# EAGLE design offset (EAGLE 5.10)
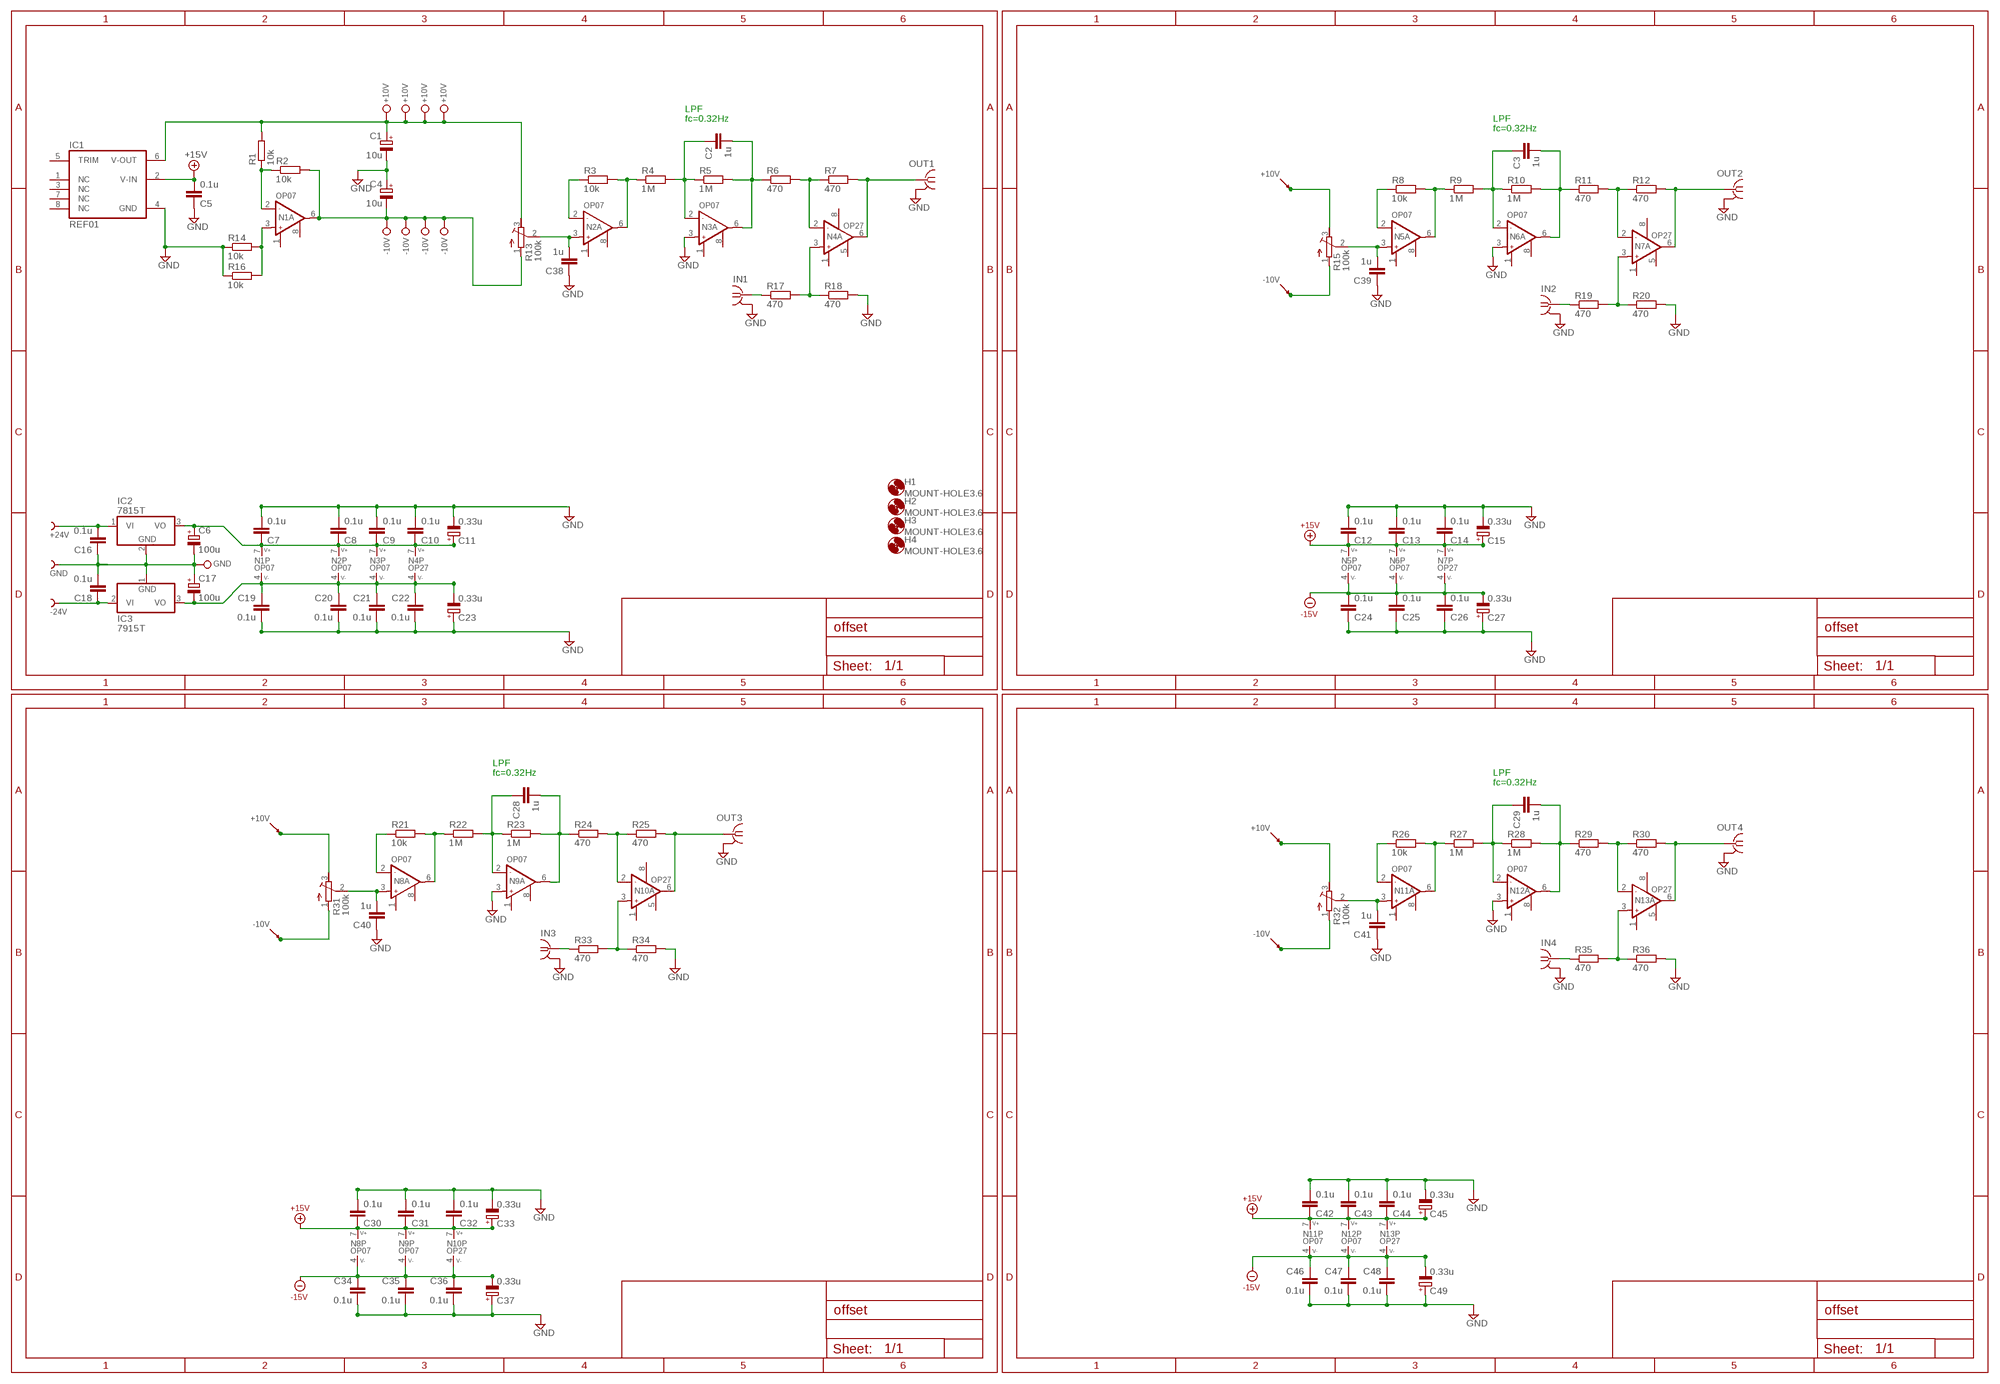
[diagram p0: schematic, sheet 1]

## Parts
+24V  XPIN  [XPIN]
-24V  XPIN  [XPIN]
C1  10u  CPOL-EUE5-5  [E5-5]
C2  1u  C-EU050-035X075  [C050-035X075]
C3  1u  C-EU050-035X075  [C050-035X075]
C4  10u  CPOL-EUE5-5  [E5-5]
C5  0.1u  C-EU050-035X075  [C050-035X075]
C6  100u  CPOL-EUE5-8.5  [E5-8,5]
C7  0.1u  C-EU050-035X075  [C050-035X075]
C8  0.1u  C-EU050-035X075  [C050-035X075]
C9  0.1u  C-EU050-035X075  [C050-035X075]
C10  0.1u  C-EU050-035X075  [C050-035X075]
C11  0.33u  CPOL-EUE5-5  [E5-5]
C12  0.1u  C-EU050-035X075  [C050-035X075]
C13  0.1u  C-EU050-035X075  [C050-035X075]
C14  0.1u  C-EU050-035X075  [C050-035X075]
C15  0.33u  CPOL-EUE5-5  [E5-5]
C16  0.1u  C-EU050-035X075  [C050-035X075]
C17  100u  CPOL-EUE5-8.5  [E5-8,5]
C18  0.1u  C-EU050-035X075  [C050-035X075]
C19  0.1u  C-EU050-035X075  [C050-035X075]
C20  0.1u  C-EU050-035X075  [C050-035X075]
C21  0.1u  C-EU050-035X075  [C050-035X075]
C22  0.1u  C-EU050-035X075  [C050-035X075]
C23  0.33u  CPOL-EUE5-5  [E5-5]
C24  0.1u  C-EU050-035X075  [C050-035X075]
C25  0.1u  C-EU050-035X075  [C050-035X075]
C26  0.1u  C-EU050-035X075  [C050-035X075]
C27  0.33u  CPOL-EUE5-5  [E5-5]
C28  1u  C-EU050-035X075  [C050-035X075]
C29  1u  C-EU050-035X075  [C050-035X075]
C30  0.1u  C-EU050-035X075  [C050-035X075]
C31  0.1u  C-EU050-035X075  [C050-035X075]
C32  0.1u  C-EU050-035X075  [C050-035X075]
C33  0.33u  CPOL-EUE5-5  [E5-5]
C34  0.1u  C-EU050-035X075  [C050-035X075]
C35  0.1u  C-EU050-035X075  [C050-035X075]
C36  0.1u  C-EU050-035X075  [C050-035X075]
C37  0.33u  CPOL-EUE5-5  [E5-5]
C38  1u  C-EU050-035X075  [C050-035X075]
C39  1u  C-EU050-035X075  [C050-035X075]
C40  1u  C-EU050-035X075  [C050-035X075]
C41  1u  C-EU050-035X075  [C050-035X075]
C42  0.1u  C-EU050-035X075  [C050-035X075]
C43  0.1u  C-EU050-035X075  [C050-035X075]
C44  0.1u  C-EU050-035X075  [C050-035X075]
C45  0.33u  CPOL-EUE5-5  [E5-5]
C46  0.1u  C-EU050-035X075  [C050-035X075]
C47  0.1u  C-EU050-035X075  [C050-035X075]
C48  0.1u  C-EU050-035X075  [C050-035X075]
C49  0.33u  CPOL-EUE5-5  [E5-5]
GND  XPIN  [XPIN]
H1  MOUNT-HOLE3.6  [3,6]
H2  MOUNT-HOLE3.6  [3,6]
H3  MOUNT-HOLE3.6  [3,6]
H4  MOUNT-HOLE3.6  [3,6]
IC1  REF01  REF01HP  [DIL08]
IC2  7815T  [TO220H]
IC3  7915T  [TO220H]
IN1  BU-SMA-V  [BU-SMA-V]
IN2  BU-SMA-V  [BU-SMA-V]
IN3  BU-SMA-V  [BU-SMA-V]
IN4  BU-SMA-V  [BU-SMA-V]
N1  OP07  [DIP08_N]
N2  OP07  [DIP08_N]
N3  OP07  [DIP08_N]
N4  OP27  AD797  [DIP08_L]
N5  OP07  [DIP08_N]
N6  OP07  [DIP08_N]
N7  OP27  AD797  [DIP08_L]
N8  OP07  [DIP08_N]
N9  OP07  [DIP08_N]
N10  OP27  AD797  [DIP08_L]
N11  OP07  [DIP08_N]
N12  OP07  [DIP08_N]
N13  OP27  AD797  [DIP08_L]
OUT1  BU-SMA-V  [BU-SMA-V]
OUT2  BU-SMA-V  [BU-SMA-V]
OUT3  BU-SMA-V  [BU-SMA-V]
OUT4  BU-SMA-V  [BU-SMA-V]
R1  10k  R-EU_0207/7  [0207/7]
R2  10k  R-EU_0207/7  [0207/7]
R3  10k  R-EU_0207/7  [0207/7]
R4  1M  R-EU_0207/7  [0207/7]
R5  1M  R-EU_0207/7  [0207/7]
R6  470  R-EU_0207/7  [0207/7]
R7  470  R-EU_0207/7  [0207/7]
R8  10k  R-EU_0207/7  [0207/7]
R9  1M  R-EU_0207/7  [0207/7]
R10  1M  R-EU_0207/7  [0207/7]
R11  470  R-EU_0207/7  [0207/7]
R12  470  R-EU_0207/7  [0207/7]
R13  100k  R-TRIMM3299W  [RTRIM3299W]
R14  10k  R-EU_0207/7  [0207/7]
R15  100k  R-TRIMM3299W  [RTRIM3299W]
R16  10k  R-EU_0207/7  [0207/7]
R17  470  R-EU_0207/7  [0207/7]
R18  470  R-EU_0207/7  [0207/7]
R19  470  R-EU_0207/7  [0207/7]
R20  470  R-EU_0207/7  [0207/7]
R21  10k  R-EU_0207/7  [0207/7]
R22  1M  R-EU_0207/7  [0207/7]
R23  1M  R-EU_0207/7  [0207/7]
R24  470  R-EU_0207/7  [0207/7]
R25  470  R-EU_0207/7  [0207/7]
R26  10k  R-EU_0207/7  [0207/7]
R27  1M  R-EU_0207/7  [0207/7]
R28  1M  R-EU_0207/7  [0207/7]
R29  470  R-EU_0207/7  [0207/7]
R30  470  R-EU_0207/7  [0207/7]
R31  100k  R-TRIMM3299W  [RTRIM3299W]
R32  100k  R-TRIMM3299W  [RTRIM3299W]
R33  470  R-EU_0207/7  [0207/7]
R34  470  R-EU_0207/7  [0207/7]
R35  470  R-EU_0207/7  [0207/7]
R36  470  R-EU_0207/7  [0207/7]
X1  +10V  XPIN1  [1PIN]
X2  +10V  XPIN1  [1PIN]
X3  +10V  XPIN1  [1PIN]
X4  +10V  XPIN1  [1PIN]
X5  -10V  XPIN1  [1PIN]
X6  -10V  XPIN1  [1PIN]
X7  -10V  XPIN1  [1PIN]
X8  -10V  XPIN1  [1PIN]
X9  GND  XPIN1  [1PIN]

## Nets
GND: C1.- C4.+ C5.1 C6.- C7.2 C8.2 C9.2 C10.2 C11.- C12.2 C13.2 C14.2 C15.- C16.1 C17.+ C18.2 C19.2 C20.2 C21.2 C22.2 C23.+ C24.1 C25.1 C26.1 C27.+ C30.2 C31.2 C32.2 C33.- C34.2 C35.2 C36.2 C37.+ C38.1 C39.1 C40.1 C41.1 C42.2 C43.2 C44.2 C45.- C46.2 C47.2 C48.2 C49.+ GND.1 IC1.4(GND) IC2.2(GND) IC3.1(GND) IN1.2(GND) IN2.2(GND) IN3.2(GND) IN4.2(GND) N3.3(A:OP+) N6.3(A:OP+) N9.3(A:OP+) N12.3(A:OP+) OUT1.2(GND) OUT2.2(GND) OUT3.2(GND) OUT4.2(GND) R14.1 R16.1 R18.2 R20.2 R34.2 R36.2 X9.1
N$1: C1.+ IC1.6(V-OUT) R1.2 R13.3(A) R15.3(A) R31.3(A) R32.3(A) X1.1 X2.1 X3.1 X4.1
N$2: N7.6(A:OPO) OUT2.1 R12.2
N$3: C4.- N1.6(A:OPO) R2.2 R13.1(E) R15.1(E) R31.1(E) R32.1(E) X5.1 X6.1 X7.1 X8.1
N$4: C2.1 N3.2(A:OP-) R4.2 R5.1
N$5: C2.2 N3.6(A:OPO) R5.2 R6.1
N$6: C39.2 N5.3(A:OP+) R15.2(S)
N$7: N5.2(A:OP-) R8.1
N$8: N5.6(A:OPO) R8.2 R9.1
N$9: N7.3(A:OP+) R19.2 R20.1
N$10: IN2.1 R19.1
N$11: C38.2 N2.3(A:OP+) R13.2(S)
N$12: N2.2(A:OP-) R3.1
N$13: N1.3(A:OP+) R14.2 R16.2
N$14: N2.6(A:OPO) R3.2 R4.1
N$15: N7.2(A:OP-) R11.2 R12.1
N$16: N4.6(A:OPO) OUT1.1 R7.2
N$17: N1.2(A:OP-) R1.1 R2.1
N$20: -24V.1 C18.1 IC3.2(VI)
N$21: +24V.1 C16.2 IC2.1(VI)
N$22: C3.1 N6.2(A:OP-) R9.2 R10.1
N$23: C3.2 N6.6(A:OPO) R10.2 R11.1
N$24: N10.6(A:OPO) OUT3.1 R25.2
N$25: N4.3(A:OP+) R17.2 R18.1
N$26: C40.2 N8.3(A:OP+) R31.2(S)
N$27: N8.2(A:OP-) R21.1
N$28: N8.6(A:OPO) R21.2 R22.1
N$29: IN1.1 R17.1
N$30: N4.2(A:OP-) R6.2 R7.1
N$31: N10.3(A:OP+) R33.2 R34.1
N$32: IN3.1 R33.1
N$33: N10.2(A:OP-) R24.2 R25.1
N$36: C28.1 N9.2(A:OP-) R22.2 R23.1
N$37: C28.2 N9.6(A:OPO) R23.2 R24.1
N$38: N13.6(A:OPO) OUT4.1 R30.2
N$39: C41.2 N11.3(A:OP+) R32.2(S)
N$40: N11.2(A:OP-) R26.1
N$41: N11.6(A:OPO) R26.2 R27.1
N$42: N13.3(A:OP+) R35.2 R36.1
N$43: IN4.1 R35.1
N$44: N13.2(A:OP-) R29.2 R30.1
N$47: C29.1 N12.2(A:OP-) R27.2 R28.1
N$48: C29.2 N12.6(A:OPO) R28.2 R29.1
V+: C5.2 C6.+ C7.1 C8.1 C9.1 C10.1 C11.+ C12.1 C13.1 C14.1 C15.+ C30.1 C31.1 C32.1 C33.+ C42.1 C43.1 C44.1 C45.+ IC1.2(V-IN) IC2.3(VO) N1.7(P:V+) N2.7(P:V+) N3.7(P:V+) N4.7(P:V+) N5.7(P:V+) N6.7(P:V+) N7.7(P:V+) N8.7(P:V+) N9.7(P:V+) N10.7(P:V+) N11.7(P:V+) N12.7(P:V+) N13.7(P:V+) ; supply symbol labelled +15V, V+15V
V-: C17.- C19.1 C20.1 C21.1 C22.1 C23.- C24.2 C25.2 C26.2 C27.- C34.1 C35.1 C36.1 C37.- C46.1 C47.1 C48.1 C49.- IC3.3(VO) N1.4(P:V-) N2.4(P:V-) N3.4(P:V-) N4.4(P:V-) N5.4(P:V-) N6.4(P:V-) N7.4(P:V-) N8.4(P:V-) N9.4(P:V-) N10.4(P:V-) N11.4(P:V-) N12.4(P:V-) N13.4(P:V-) ; supply symbol labelled V-15V
Unconnected: IC1.1(NC) IC1.3(NC) IC1.5(TRIM) IC1.7(NC) IC1.8(NC) N1.1(A:OPC1) N1.8(A:OPC2) N2.1(A:OPC1) N2.8(A:OPC2) N3.1(A:OPC1) N3.8(A:OPC2) N4.1(A:OPC1) N4.5(A:OPC2) N4.8(A:OPF) N5.1(A:OPC1) N5.8(A:OPC2) N6.1(A:OPC1) N6.8(A:OPC2) N7.1(A:OPC1) N7.5(A:OPC2) N7.8(A:OPF) N8.1(A:OPC1) N8.8(A:OPC2) N9.1(A:OPC1) N9.8(A:OPC2) N10.1(A:OPC1) N10.5(A:OPC2) N10.8(A:OPF) N11.1(A:OPC1) N11.8(A:OPC2) N12.1(A:OPC1) N12.8(A:OPC2) N13.1(A:OPC1) N13.5(A:OPC2) N13.8(A:OPF)

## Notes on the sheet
- LPF
- fc=0.32Hz | LPF
- fc=0.32Hz
- LPF
- fc=0.32Hz | LPF
- fc=0.32Hz

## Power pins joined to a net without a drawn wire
GND: IN1.3(GND) IN1.4(GND) IN1.5(GND) IN2.3(GND) IN2.4(GND) IN2.5(GND) IN3.3(GND) IN3.4(GND) IN3.5(GND) IN4.3(GND) IN4.4(GND) IN4.5(GND) OUT1.3(GND) OUT1.4(GND) OUT1.5(GND) OUT2.3(GND) OUT2.4(GND) OUT2.5(GND) OUT3.3(GND) OUT3.4(GND) OUT3.5(GND) OUT4.3(GND) OUT4.4(GND) OUT4.5(GND)

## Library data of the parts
+24V -24V GND = DIVERS:XPIN
C1 C4 C6 C11 C15 C17 C23 C27 C33 C37 C45 C49 = rcl:CPOL-EU: POLARIZED CAPACITOR, European symbol
C2 C3 C5 C7-C10 C12-C14 C16 C18-C22 C24-C26 C28-C32 C34-C36 C38-C44 C46-C48 = rcl:C-EU: CAPACITOR, European symbol
H1-H4 = holes:MOUNT-HOLE: MOUNTING HOLE with drill center marker
IC1 = maxim:REF01HP: VOLTAGE REFERENCE
IC2 = linear:78*: Positive VOLTAGE REGULATOR Source: http://cache.national.com/ds/LM/LM78L05.pdf http://www.fairchildsemi.com/ds/LM/LM7805.pdf
IC3 = linear:79*: Negative VOLTAGE REGULATOR
IN1-IN4 OUT1-OUT4 = con-coax:BU-SMA-V: FEMALE SMA CONNECTOR Radiall distributor RS 112-3794
N1-N3 N5 N6 N8 N9 N11 N12 = opamp:OP07
N4 N7 N10 N13 = opamp:AD797
R1-R12 R14 R16-R30 R33-R36 = rcl:R-EU_: RESISTOR, European symbol
R13 R15 R31 R32 = rcl:R-TRIMM: Trimm resistor
X1-X9 = DRAW:XPIN1

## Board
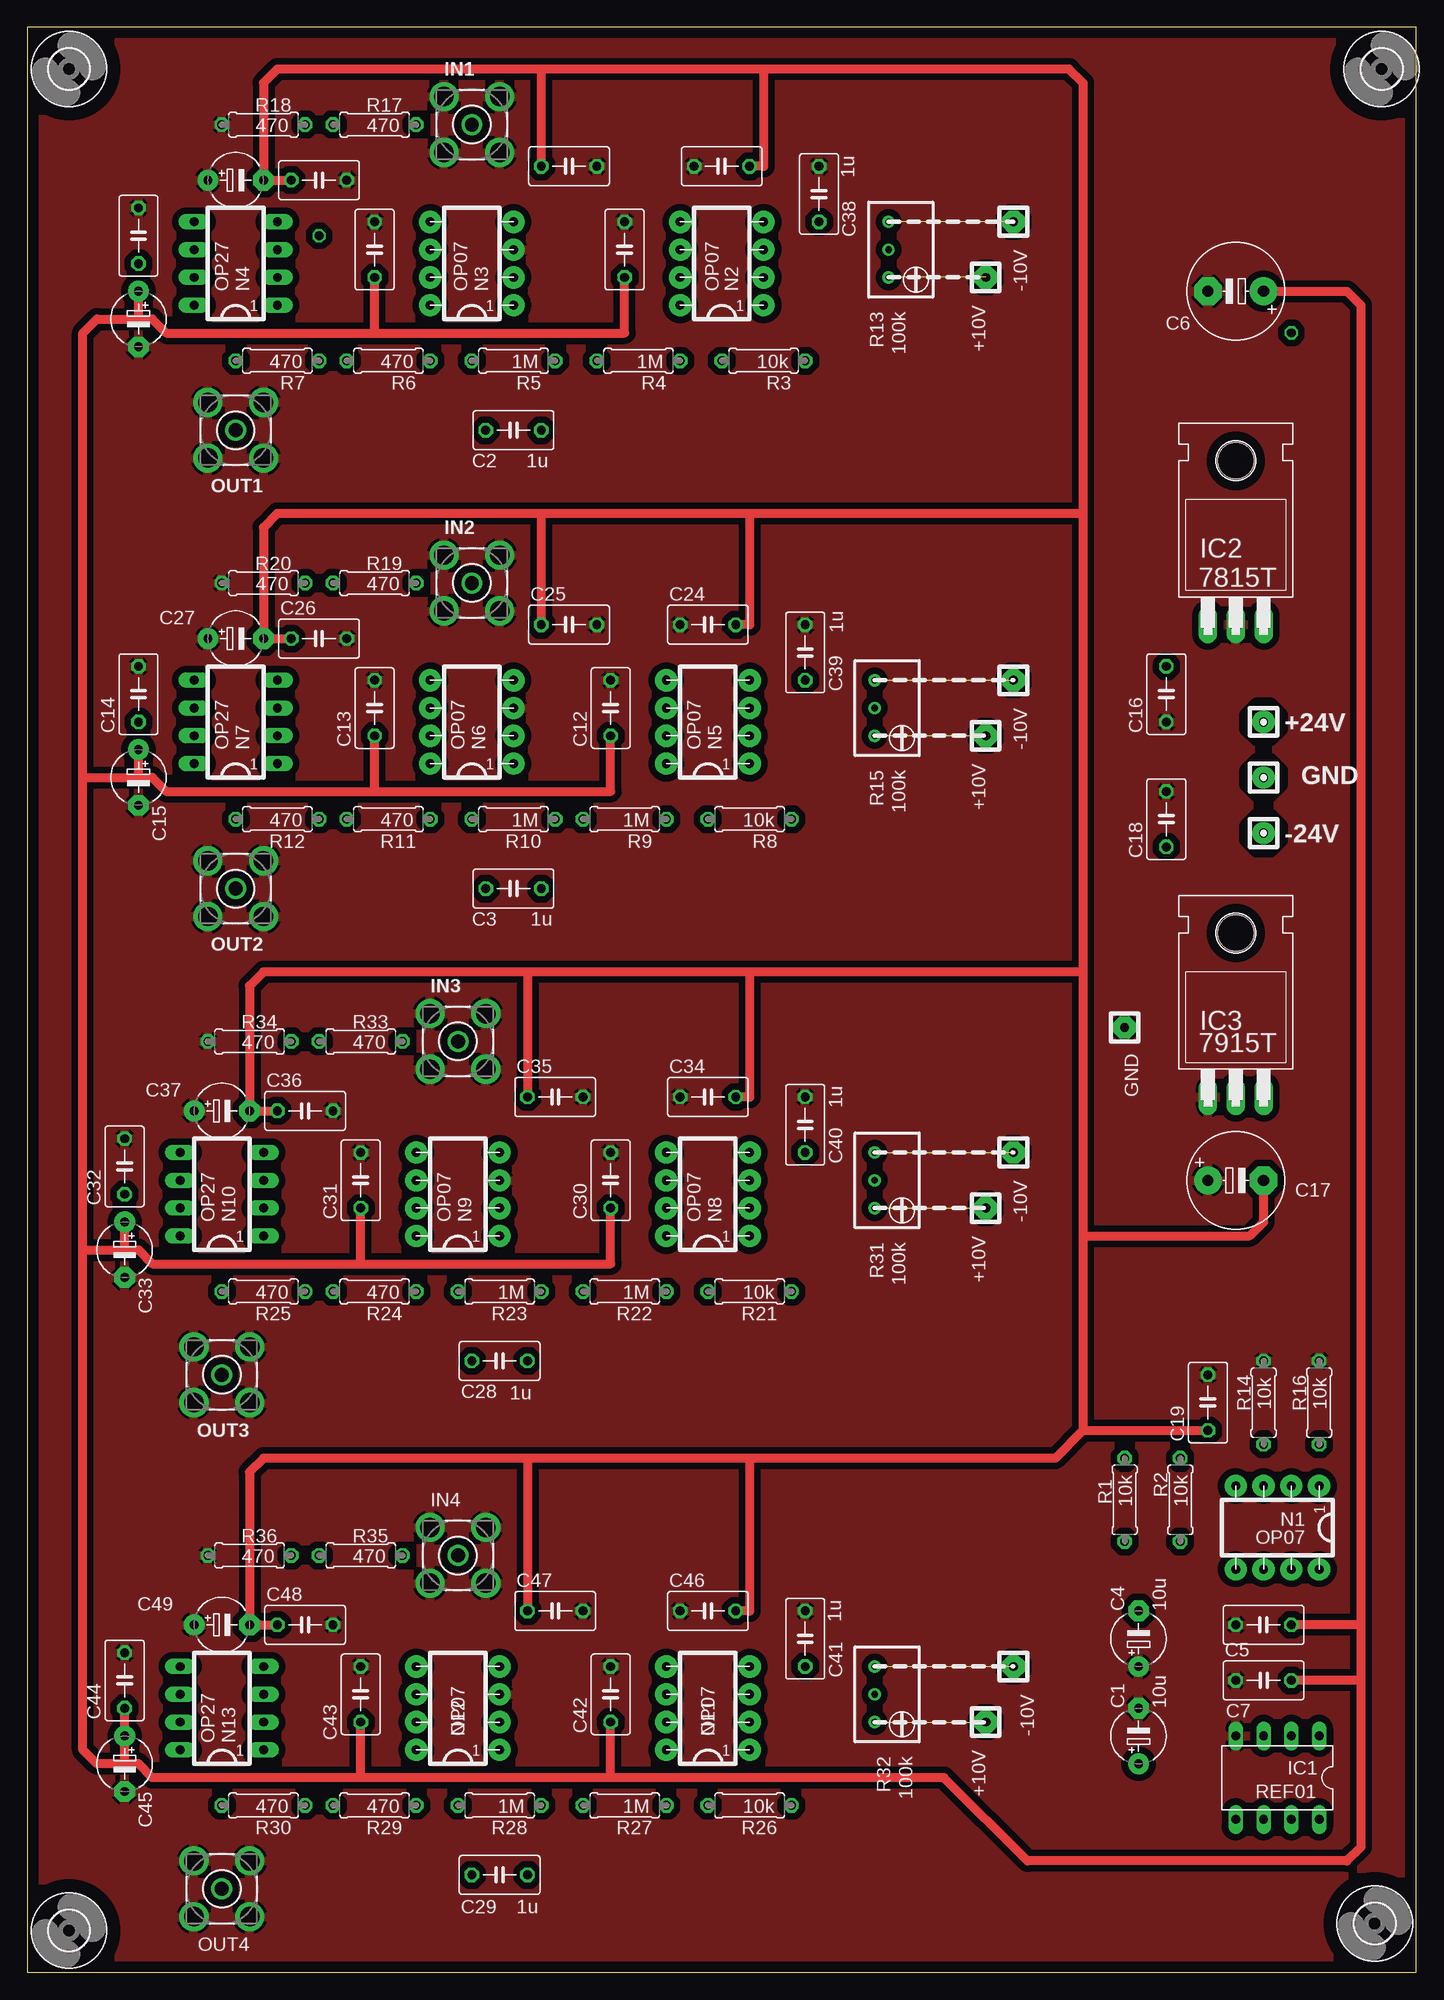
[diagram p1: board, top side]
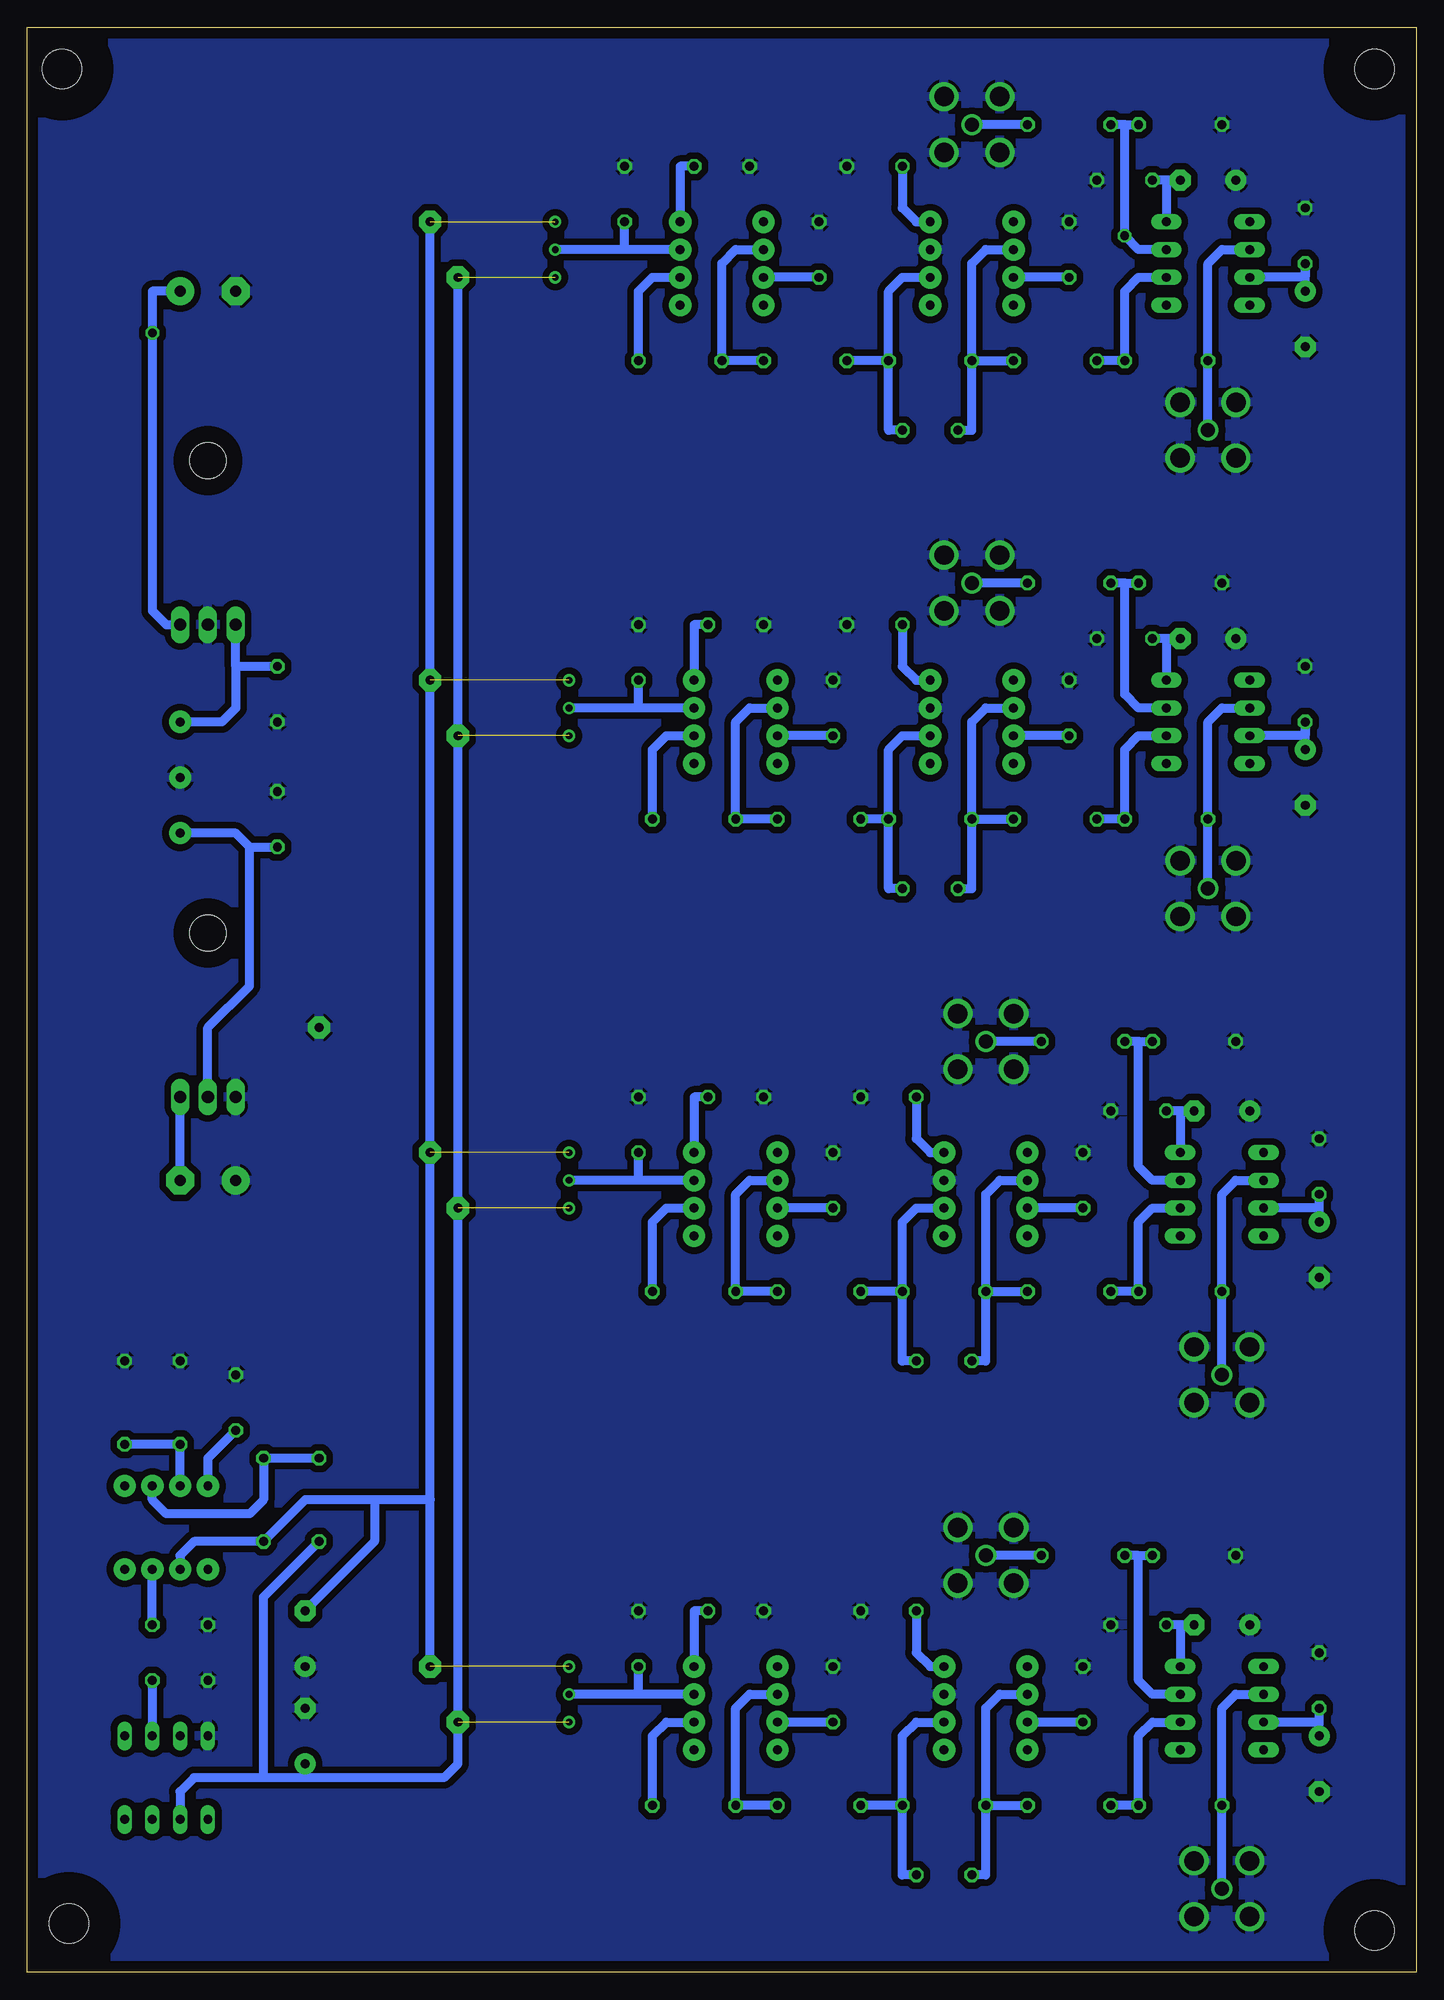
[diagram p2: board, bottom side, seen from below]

Size 127 x 177.8 mm. Coordinates in mm from the lower left corner, seen from the top.
Outline: 0,0 127,0 127,177.8 0,177.8 0,0
Copper layers (1*16): Top 0.035mm / dielectric 1.5mm / Bottom 0.035mm
Design rules "default": minimum track width 10mil, minimum drill 24mil, track to track 8mil, track to pad 8mil, pad to pad 8mil, via to via 8mil, smd to smd 8mil, copper to edge 40mil, drill to drill 8mil, minimum pad ring 10mil, minimum via ring 8mil, stop-mask expansion 4mil, vias tented up to drill 0mil, thermal gap 10mil

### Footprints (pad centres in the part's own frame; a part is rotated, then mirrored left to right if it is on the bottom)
XPIN = drill 0.813 pad 2.032 round: 1 0,0
E5-5 = drill 0.813 pad 1.905 round: + -2.54,0 | drill 0.813 pad 1.905 octagon: - 2.54,0
C050-035X075 = drill 0.813 octagon: 1 -2.54,0; 2 2.54,0
E5-8,5 = drill 1.016 pad 2.54 round: + -2.54,0 | drill 1.016 pad 2.54 octagon: - 2.54,0
3,6 = hole 3.6: 0,0
DIL08 = drill 0.813 long: 1 -3.81,-3.81; 2 -1.27,-3.81; 3 1.27,-3.81; 4 3.81,-3.81; 5 3.81,3.81; 6 1.27,3.81; 7 -1.27,3.81; 8 -3.81,3.81
TO220H = drill 1.118 long: 1 -2.54,-10.16; 2 0,-10.16; 3 2.54,-10.16 | hole 3.302: 0,4.826
BU-SMA-V = drill 1.27 round: 1 0,0 | drill 1.778 round: 2 -2.55,2.55; 3 2.55,2.55; 4 2.55,-2.55; 5 -2.55,-2.55
DIP08_N = drill 0.813 pad 2.032 round: 1 0,0; 2 2.54,0; 3 5.08,0; 4 7.62,0; 5 7.62,7.62; 6 5.08,7.62; 7 2.54,7.62; 8 0,7.62
DIP08_L = drill 0.813 pad 1.397 long: 1 0,0; 2 2.54,0; 3 5.08,0; 4 7.62,0; 5 7.62,7.62; 6 5.08,7.62; 7 2.54,7.62; 8 0,7.62
0207/7 = drill 0.813 octagon: 1 -3.81,0; 2 3.81,0
RTRIM3299W = drill 0.61 round: 1 1.27,-2.54; 2 1.27,0; 3 1.27,2.54
1PIN = drill 0.813 pad 2.032 octagon: 1 0,0

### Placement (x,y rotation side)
+24V  113.03,114.3 0 top
-24V  113.03,104.14 0 top
C1  101.6,21.59 90 top
C2  44.45,140.97 180 top
C3  44.45,99.06 180 top
C4  101.6,30.48 90 top
C5  113.03,26.67 0 top
C6  110.49,153.67 180 top
C7  113.03,31.75 180 top
C8  54.61,157.48 90 top
C9  31.75,157.48 90 top
C10  10.16,158.75 90 top
C11  10.16,151.13 270 top
C12  53.34,115.57 90 top
C13  31.75,115.57 90 top
C14  10.16,116.84 90 top
C15  10.16,109.22 270 top
C16  104.14,116.84 90 top
C17  110.49,72.39 0 top
C18  104.14,105.41 90 top
C19  107.95,52.07 90 top
C20  63.5,165.1 180 top
C21  49.53,165.1 0 top
C22  26.67,163.83 0 top
C23  19.05,163.83 0 top
C24  62.23,123.19 0 top
C25  49.53,123.19 180 top
C26  26.67,121.92 180 top
C27  19.05,121.92 0 top
C28  43.18,55.88 180 top
C29  43.18,8.89 180 top
C30  53.34,72.39 90 top
C31  30.48,72.39 90 top
C32  8.89,73.66 90 top
C33  8.89,66.04 270 top
C34  62.23,80.01 180 top
C35  48.26,80.01 0 top
C36  25.4,78.74 0 top
C37  17.78,78.74 0 top
C38  72.39,162.56 270 top
C39  71.12,120.65 270 top
C40  71.12,77.47 270 top
C41  71.12,30.48 270 top
C42  53.34,25.4 90 top
C43  30.48,25.4 90 top
C44  8.89,26.67 90 top
C45  8.89,19.05 270 top
C46  62.23,33.02 180 top
C47  48.26,33.02 0 top
C48  25.4,31.75 0 top
C49  17.78,31.75 0 top
GND  113.03,109.22 0 top
H1  3.81,3.81 0 top
H2  123.83,173.99 0 top
H3  123.19,4.45 0 top
H4  3.81,173.99 0 top
IC1  114.3,17.78 180 top
IC2  110.49,133.35 0 top
IC3  110.49,90.17 0 top
IN1  40.64,168.91 0 top
IN2  40.64,127 0 top
IN3  39.37,85.09 0 top
IN4  39.37,38.1 0 top
N1  118.11,44.45 180 top
N2  67.31,152.4 90 top
N3  44.45,152.4 90 top
N4  22.86,152.4 90 top
N5  66.04,110.49 90 top
N6  44.45,110.49 90 top
N7  22.86,110.49 90 top
N8  66.04,67.31 90 top
N9  43.18,67.31 90 top
N10  21.59,67.31 90 top
N11  66.04,20.32 90 top
N12  43.18,20.32 90 top
N13  21.59,20.32 90 top
OUT1  19.05,140.97 180 top
OUT2  19.05,99.06 180 top
OUT3  17.78,54.61 180 top
OUT4  17.78,7.62 180 top
R1  100.33,43.18 270 top
R2  105.41,43.18 270 top
R3  67.31,147.32 180 top
R4  55.88,147.32 180 top
R5  44.45,147.32 180 top
R6  33.02,147.32 180 top
R7  22.86,147.32 180 top
R8  66.04,105.41 180 top
R9  54.61,105.41 180 top
R10  44.45,105.41 180 top
R11  33.02,105.41 180 top
R12  22.86,105.41 180 top
R13  80.01,157.48 180 top
R14  113.03,52.07 270 top
R15  78.74,115.57 180 top
R16  118.11,52.07 270 top
R17  31.75,168.91 180 top
R18  21.59,168.91 180 top
R19  31.75,127 180 top
R20  21.59,127 180 top
R21  66.04,62.23 180 top
R22  54.61,62.23 180 top
R23  43.18,62.23 180 top
R24  31.75,62.23 180 top
R25  21.59,62.23 180 top
R26  66.04,15.24 180 top
R27  54.61,15.24 180 top
R28  43.18,15.24 180 top
R29  31.75,15.24 180 top
R30  21.59,15.24 180 top
R31  78.74,72.39 180 top
R32  78.74,25.4 180 top
R33  30.48,85.09 180 top
R34  20.32,85.09 180 top
R35  30.48,38.1 180 top
R36  20.32,38.1 180 top
X1  87.63,22.86 270 top
X2  87.63,113.03 270 top
X3  87.63,69.85 270 top
X4  87.63,154.94 270 top
X5  90.17,27.94 270 top
X6  90.17,74.93 270 top
X7  90.17,118.11 270 top
X8  90.17,160.02 270 top
X9  100.33,86.36 270 top

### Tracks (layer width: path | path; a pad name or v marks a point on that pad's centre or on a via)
GND
  pour Bottom (isolate 0.61): 0,177.8 127,177.8 127,0 0,0
  pour Top (isolate 0.61): 0,177.8 127,177.8 127,0 0,0
N$1  (4 unrouted)
  Bottom 0.813: 105.41,17.78 105.41,34.29 R1.2 | IC1.6 113.03,16.51 111.76,17.78 105.41,17.78 | 101.6,17.78 105.41,17.78 | 101.6,17.78 C1.+ | 101.6,17.78 88.9,17.78 87.63,19.05 X1.1 X3.1 X2.1 X4.1
N$2
  Bottom 0.813: N7.6 17.78,115.57 19.05,114.3 R12.2 OUT2.1
N$3  (4 unrouted)
  Bottom 0.813: N1.6 113.03,38.1 111.76,39.37 R2.2 101.6,43.18 95.25,43.18 | 95.25,43.18 95.25,39.37 C4.- | 90.17,43.18 X6.1 X7.1 X8.1 | X5.1 90.17,43.18 | 90.17,43.18 95.25,43.18
N$4
  Bottom 0.813: R5.1 R4.2 | R5.1 48.26,140.97 C2.1 | R5.1 48.26,153.67 46.99,154.94 N3.2
N$5
  Bottom 0.813: C2.2 40.64,140.97 R5.2 | R5.2 40.64,156.21 39.37,157.48 N3.6 | R5.2 R6.1
N$6
  Bottom 0.813: N5.3 71.12,115.57 | 71.12,115.57 R15.2 | 71.12,115.57 C39.2
N$7
  Bottom 0.813: N5.2 68.58,113.03 69.85,111.76 R8.1
N$8
  Bottom 0.813: N5.6 60.96,115.57 62.23,114.3 R8.2 R9.1
N$9
  Bottom 0.813: N7.3 25.4,115.57 26.67,116.84 26.67,127 | 26.67,127 R20.1 | 26.67,127 R19.2
N$10
  Bottom 0.813: R19.1 IN2.1
N$11
  Bottom 0.813: N2.3 72.39,157.48 | 72.39,157.48 R13.2 | 72.39,157.48 C38.2
N$12
  Bottom 0.813: N2.2 69.85,154.94 71.12,153.67 R3.1
N$13
  Bottom 0.813: N1.3 R14.2 R16.2
N$14
  Bottom 0.813: N2.6 62.23,157.48 63.5,156.21 R3.2 R4.1
N$15
  Bottom 0.813: R11.2 R12.1 26.67,111.76 25.4,113.03 N7.2
N$16
  Bottom 0.813: N4.6 17.78,157.48 19.05,156.21 R7.2 OUT1.1
N$17
  Bottom 0.813: R1.1 R2.1 105.41,43.18 106.68,41.91 114.3,41.91 115.57,43.18 N1.2
N$20
  Bottom 0.813: -24V.1 107.95,104.14 106.68,102.87 | 106.68,102.87 106.68,90.17 110.49,86.36 IC3.2 | 106.68,102.87 C18.1
N$21
  Bottom 0.813: 107.95,119.38 107.95,115.57 109.22,114.3 +24V.1 | 107.95,119.38 IC2.1 | C16.2 107.95,119.38
N$22
  Bottom 0.813: R10.1 R9.2 | N6.2 46.99,113.03 48.26,111.76 R10.1 | R10.1 48.26,99.06 C3.1
N$23
  Bottom 0.813: C3.2 40.64,99.06 R10.2 | R10.2 40.64,114.3 39.37,115.57 N6.6 | R10.2 R11.1
N$24
  Bottom 0.813: N10.6 16.51,72.39 17.78,71.12 R25.2 OUT3.1
N$25  (via drill 0.8)
  Bottom 0.813: N4.3 25.4,157.48 v26.67,158.75 26.67,168.91 | 26.67,168.91 R18.1 | 26.67,168.91 R17.2
N$26
  Bottom 0.813: N8.3 71.12,72.39 | 71.12,72.39 R31.2 | 71.12,72.39 C40.2
N$27
  Bottom 0.813: N8.2 68.58,69.85 69.85,68.58 R21.1
N$28
  Bottom 0.813: R22.1 R21.2 62.23,71.12 60.96,72.39 N8.6
N$29
  Bottom 0.813: R17.1 IN1.1
N$30
  Bottom 0.813: R6.2 R7.1 26.67,153.67 25.4,154.94 N4.2
N$31
  Bottom 0.813: 25.4,85.09 R34.1 | 25.4,85.09 R33.2 | N10.3 24.13,72.39 25.4,73.66 25.4,85.09
N$32
  Bottom 0.813: R33.1 IN3.1
N$33
  Bottom 0.813: N10.2 24.13,69.85 25.4,68.58 R25.1 R24.2
N$36
  Bottom 0.813: R23.1 46.99,55.88 C28.1 | R23.1 R22.2 | N9.2 45.72,69.85 46.99,68.58 R23.1
N$37
  Bottom 0.813: R23.2 R24.1 | N9.6 38.1,72.39 39.37,71.12 R23.2 | R23.2 39.37,55.88 C28.2
N$38
  Bottom 0.813: N13.6 16.51,25.4 17.78,24.13 R30.2 OUT4.1
N$39
  Bottom 0.813: N11.3 71.12,25.4 | 71.12,25.4 R32.2 | 71.12,25.4 C41.2
N$40
  Bottom 0.813: N11.2 68.58,22.86 69.85,21.59 R26.1
N$41
  Bottom 0.813: N11.6 60.96,25.4 62.23,24.13 R26.2 R27.1
N$42
  Bottom 0.813: N13.3 24.13,25.4 25.4,26.67 25.4,38.1 | 25.4,38.1 R36.1 | 25.4,38.1 R35.2
N$43
  Bottom 0.813: R35.1 IN4.1
N$44
  Bottom 0.813: R29.2 R30.1 25.4,21.59 24.13,22.86 N13.2
N$47
  Bottom 0.813: R28.1 R27.2 | R28.1 46.99,21.59 45.72,22.86 N12.2 | R28.1 46.99,8.89 C29.1
N$48
  Bottom 0.813: R28.2 39.37,8.89 C29.2 | R28.2 R29.1 | N12.6 38.1,25.4 39.37,24.13 R28.2
V+  (via drill 0.8)
  Top 0.813: 31.75,149.86 54.61,149.86 C8.1 | 31.75,149.86 C9.1 | 31.75,107.95 53.34,107.95 C12.1 | 31.75,107.95 12.7,107.95 11.43,109.22 10.16,109.22 | 31.75,107.95 C13.1 | 30.48,64.77 53.34,64.77 C30.1 | 30.48,64.77 C31.1 | C44.1 C45.+ 8.89,19.05 | 30.48,17.78 11.43,17.78 10.16,19.05 8.89,19.05 | 53.34,17.78 30.48,17.78 | 30.48,17.78 C43.1 | 53.34,17.78 C42.1 | 53.34,17.78 83.82,17.78 91.44,10.16 120.65,10.16 121.92,11.43 121.92,26.67 | 121.92,31.75 121.92,26.67 | 121.92,31.75 C7.1 | 121.92,26.67 C5.2 | 5.08,66.04 5.08,109.22 | 5.08,109.22 5.08,149.86 6.35,151.13 10.16,151.13 | C6.+ 120.65,153.67 121.92,152.4 121.92,31.75 | 31.75,149.86 12.7,149.86 11.43,151.13 10.16,151.13 | 10.16,151.13 C11.+ | 5.08,109.22 10.16,109.22 | 10.16,109.22 C15.+ | 30.48,64.77 11.43,64.77 10.16,66.04 8.89,66.04 | 5.08,66.04 8.89,66.04 | 8.89,66.04 C33.+ | 8.89,19.05 6.35,19.05 5.08,20.32 5.08,66.04
  Bottom 0.813: IC2.3 114.3,123.19 115.57,124.46 v115.57,149.86 115.57,153.67 C6.+ | C8.1 N2.7 | N4.7 10.16,154.94 C10.1 C11.+ | C9.1 N3.7 | C7.1 N1.7 | C12.1 N5.7 | N7.7 10.16,113.03 C14.1 C15.+ | C13.1 N6.7 | C30.1 N8.7 | C31.1 N9.7 | C33.+ 8.89,69.85 | 8.89,69.85 C32.1 | 8.89,69.85 N10.7 | 8.89,22.86 N13.7 | 8.89,22.86 C44.1 | C45.+ 8.89,22.86 | C43.1 N12.7 | C42.1 N11.7 | C5.2 IC1.2
V-
  Top 0.813: C48.1 C49.- 20.32,45.72 21.59,46.99 45.72,46.99 | 66.04,46.99 45.72,46.99 | 66.04,46.99 93.98,46.99 96.52,49.53 | 45.72,46.99 C47.1 | C46.1 66.04,33.02 66.04,46.99 | C36.1 C37.- 20.32,90.17 21.59,91.44 45.72,91.44 | 66.04,91.44 45.72,91.44 | 96.52,91.44 66.04,91.44 | 45.72,91.44 C35.1 | C34.1 66.04,80.01 66.04,91.44 | C26.2 C27.- 21.59,132.08 22.86,133.35 46.99,133.35 | 66.04,133.35 46.99,133.35 | 96.52,133.35 66.04,133.35 | 46.99,133.35 C25.2 | C24.2 66.04,123.19 66.04,133.35 | C22.1 C23.- 21.59,172.72 22.86,173.99 46.99,173.99 | 67.31,173.99 95.25,173.99 96.52,172.72 96.52,133.35 | 67.31,173.99 46.99,173.99 | 46.99,173.99 C21.1 | C20.1 67.31,165.1 67.31,173.99 | C17.- 113.03,68.58 111.76,67.31 96.52,67.31 | 96.52,67.31 96.52,49.53 | 96.52,91.44 96.52,67.31 | 96.52,133.35 96.52,91.44 | 96.52,49.53 C19.1
  Bottom 0.813: C17.- IC3.3 | C20.1 67.31,165.1 N2.4 | 22.86,163.83 N4.4 | 22.86,163.83 C22.1 | C23.- 22.86,163.83 | C21.1 46.99,161.29 45.72,160.02 N3.4 | N5.4 66.04,123.19 C24.2 | N6.4 45.72,118.11 46.99,119.38 C25.2 | 22.86,121.92 N7.4 | 22.86,121.92 C26.2 | C27.- 22.86,121.92 | N8.4 66.04,80.01 C34.1 | N9.4 44.45,74.93 45.72,76.2 C35.1 | 21.59,78.74 N10.4 | C37.- 21.59,78.74 | 21.59,78.74 C36.1 | 21.59,31.75 N13.4 | C49.- 21.59,31.75 | 21.59,31.75 C48.1 | N12.4 44.45,27.94 45.72,29.21 C47.1 | N11.4 66.04,33.02 C46.1 | N1.4 110.49,46.99 C19.1

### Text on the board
tNames: -10V | +10V | -10V | +10V | GND | -10V | +10V | -10V | +10V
